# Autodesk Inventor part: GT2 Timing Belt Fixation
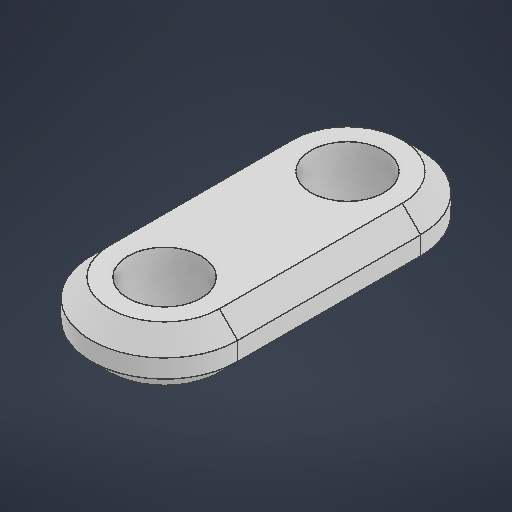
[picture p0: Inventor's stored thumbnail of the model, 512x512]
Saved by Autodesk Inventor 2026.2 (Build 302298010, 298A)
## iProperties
Created: 2026-04
Part Number: GT2 Timing Belt Fixation
Material: 일반
Document SubType Name: Modeling
Designer: work
Density: 1 g/cm^3
Appearance: 기본값
Author: work
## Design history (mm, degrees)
sketch "스케치1"
  geometry: L1 (0, 0)-(0, -10); L2 (-4, 0)-(-4, -10); L3 (4, -10)-(4, 0); C1 r 2 at (0, 0); C2 r 2 at (0, -10); A1 r 4 centre (0, 0) between (4, 0) and (-4, 0); A2 r 4 centre (0, -10) between (-4, -10) and (4, -10); 1 further point
  constraints: 8 end point, 4 centre point, 4 point on circle, 4 tangent, 2 coincident, 1 midpoint, 1 parallel, 1 vertical
  dimensions: "d0" = 10 distance of L1.start L1.end; "d1" = 8 diameter of A2; "d2" = 4 diameter of C1; "d3" = 4 diameter of C2
extrude "돌출1" new body sketch "스케치1" distance "d4" = 3; taper "d5" = 0 deg
chamfer "모따기1" distance "d6" = 1; stored, may be unused: second distance "d7" = 2, angle "d8" = 45 deg
node "솔리드1"
